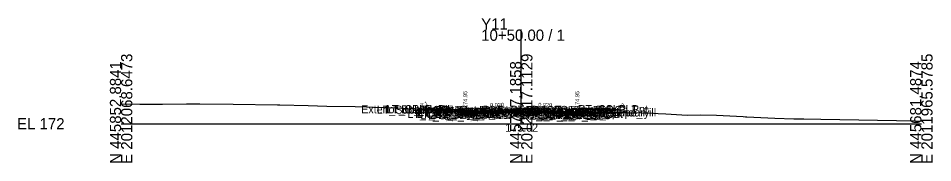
# Model space of a CAD drawing. Extents: x -26 to 203, y -10 to 3517.
# Drawn here: x -25.7 to 202.8, y 990.3 to 1026.3 of the extents above; entities that cross this region are included whole.
import ezdxf

# ---------------------------------------------------------------- set-up
doc = ezdxf.new("R2010")
doc.units = 0
for name, color, linetype in [('Default', 7, 'Continuous'), ('Exist CMT Pavement', 7, 'Continuous'), ('Exist Cross Section Cell', 7, 'Continuous'), ('Exist XS Center Line Elevation Label', 7, 'Continuous'), ('Exist XS Ground Line', 7, 'Continuous'), ('Prop CMT Conc Surface', 7, 'Continuous'), ('Prop CMT Concrete Structures', 7, 'Continuous'), ('Prop CMT Pvmt Course 1', 7, 'Continuous'), ('Prop CMT Pvmt Course 1 CG', 7, 'Continuous'), ('Prop CMT Pvmt Course 1 Wedge', 7, 'Continuous'), ('Prop CMT Pvmt Course 2', 7, 'Continuous'), ('Prop CMT Pvmt Course 2 Wedge', 7, 'Continuous'), ('Prop CMT Pvmt Course 3', 7, 'Continuous'), ('Prop CMT Pvmt Course 3 Wedge', 7, 'Continuous'), ('Prop CMT Pvmt Surface', 7, 'Continuous'), ('Prop CMT Pvmt Wedge Surface 1', 7, 'Continuous'), ('Prop CMT Pvmt Wedge Surface 2', 7, 'Continuous'), ('Prop CMT Pvmt Wedge Surface 3', 7, 'Continuous'), ('Prop CMT Slope Grass', 7, 'Continuous'), ('Prop CMT Subgrade Earthwork', 7, 'Continuous'), ('Prop XS Earthwork Shape', 7, 'Continuous'), ('Prop XS Hydro Elevations', 7, 'Continuous'), ('Prop XS SE Text', 7, 'Continuous'), ('Prop XS Side Slope Text', 7, 'Continuous'), ('Scratch_Level_0', 7, 'Continuous')]:
    doc.layers.add(name, color=color, linetype=linetype)

msp = doc.modelspace()

# ---------------------------------------------------------------- linework, layer by layer
at = {"layer": 'Exist CMT Pavement'}
msp.add_line((100, 1003.02), (110.98, 1002.65), dxfattribs=at)
msp.add_lwpolyline([(100, 1003.02), (99.41, 1003.04), (89.01, 1002.74)], dxfattribs=at)
at = {"layer": 'Exist Cross Section Cell'}
for p, q in [((100, 1000), (100, 1023.47)), ((0, 1000), (100, 1000)), ((100, 1000), (200, 1000))]:
    msp.add_line(p, q, dxfattribs=at)
at = {"layer": 'Exist XS Ground Line'}
msp.add_lwpolyline([(0, 1004.93), (4.7, 1004.9), (10.32, 1004.9), (16.37, 1005), (19.66, 1004.94), (28.04, 1004.91), (39.07, 1004.72), (39.71, 1004.7), (46.76, 1004.52), (51.38, 1004.41), (58.47, 1004.28), (61.33, 1004.19), (63.05, 1004.12), (68.62, 1003.94), (74.72, 1003.66), (77.51, 1003.51), (86.81, 1002.91), (87.99, 1002.76), (88.31, 1002.72), (94.9, 1002.9), (99.41, 1003.04), (100, 1003.02), (109.78, 1002.69), (111.37, 1002.63), (112.46, 1002.77), (114.66, 1002.75), (118.15, 1002.73), (126.92, 1002.83), (133.08, 1002.63), (134.21, 1002.59), (136.1, 1002.49), (141.5, 1002.16), (144.75, 1002.22), (148.79, 1002.18), (155.51, 1001.77), (156.07, 1001.73), (156.42, 1001.72), (163.36, 1001.43), (168.09, 1001.26), (170.65, 1001.22), (174.91, 1001.14), (198.53, 1000.71), (200, 1000.68)], dxfattribs=at)
at = {"layer": 'Prop CMT Conc Surface'}
for points in [[(86, 1002.95), (86, 1003.45), (85.5, 1003.45)], [(114, 1002.95), (114, 1003.45), (114.5, 1003.45)], [(88, 1003.07), (86, 1002.95)], [(112, 1003.07), (114, 1002.95)]]:
    msp.add_lwpolyline(points, dxfattribs=at)
at = {"layer": 'Prop CMT Concrete Structures'}
for points in [[(88, 1003.07), (86, 1002.95), (86, 1003.45), (85.5, 1003.45)], [(85.5, 1003.45), (85.5, 1002.44), (88, 1002.49)], [(112, 1003.07), (114, 1002.95), (114, 1003.45), (114.5, 1003.45)], [(114.5, 1003.45), (114.5, 1002.44), (112, 1002.49)], [(88, 1002.49), (88, 1003.07)], [(112, 1002.49), (112, 1003.07)]]:
    msp.add_lwpolyline(points, dxfattribs=at)
at = {"layer": 'Prop CMT Pvmt Course 1'}
for points in [[(100, 1003.31), (88, 1003.07)], [(100, 1003.06), (100, 1003.31)], [(100, 1003.31), (112, 1003.07)], [(100, 1003.06), (100, 1003.31)], [(88, 1003.07), (88, 1002.82)], [(88, 1002.82), (89, 1002.84)], [(89, 1002.97), (100, 1003.19)], [(89, 1002.84), (89, 1002.97)], [(100, 1003.19), (100, 1003.06), (100, 1003.06)], [(111, 1002.97), (100, 1003.19)], [(100, 1003.19), (100, 1003.06), (100, 1003.06)], [(111, 1002.84), (111, 1002.97)], [(112, 1002.82), (111, 1002.84)], [(112, 1003.07), (112, 1002.82)]]:
    msp.add_lwpolyline(points, dxfattribs=at)
at = {"layer": 'Prop CMT Pvmt Course 1 CG'}
for points in [[(88, 1002.49), (85, 1002.43), (84.7, 1002.13)], [(84.7, 1002.13), (88, 1002.2)], [(88, 1002.2), (88, 1002.49)], [(112, 1002.49), (115, 1002.43), (115.3, 1002.13)], [(112, 1002.2), (112, 1002.49)], [(115.3, 1002.13), (112, 1002.2)]]:
    msp.add_lwpolyline(points, dxfattribs=at)
at = {"layer": 'Prop CMT Pvmt Course 1 Wedge'}
for points in [[(100, 1003.19), (89, 1002.97)], [(100, 1003.19), (111, 1002.97)]]:
    msp.add_lwpolyline(points, dxfattribs=at)
at = {"layer": 'Prop CMT Pvmt Course 2'}
for points in [[(89, 1002.84), (88, 1002.82)], [(88, 1002.82), (88, 1002.57)], [(88, 1002.57), (89, 1002.59)], [(89, 1002.59), (89, 1002.84)], [(111, 1002.59), (111, 1002.84)], [(111, 1002.84), (112, 1002.82)], [(112, 1002.57), (111, 1002.59)], [(112, 1002.82), (112, 1002.57)]]:
    msp.add_lwpolyline(points, dxfattribs=at)
at = {"layer": 'Prop CMT Pvmt Course 2 Wedge'}
for points in [[(100, 1003.06), (89, 1002.84)], [(100, 1003.06), (111, 1002.84)]]:
    msp.add_lwpolyline(points, dxfattribs=at)
at = {"layer": 'Prop CMT Pvmt Course 3'}
for points in [[(89, 1002.59), (88, 1002.57)], [(88, 1002.57), (88, 1002.2)], [(88, 1002.2), (89, 1002.22)], [(89, 1002.22), (89, 1002.59)], [(111, 1002.59), (112, 1002.57)], [(111, 1002.22), (111, 1002.59)], [(112, 1002.2), (111, 1002.22)], [(112, 1002.57), (112, 1002.2)]]:
    msp.add_lwpolyline(points, dxfattribs=at)
at = {"layer": 'Prop CMT Pvmt Course 3 Wedge'}
for points in [[(100, 1002.81), (89, 1002.59)], [(100, 1002.81), (111, 1002.59)]]:
    msp.add_lwpolyline(points, dxfattribs=at)
at = {"layer": 'Prop CMT Pvmt Surface'}
for points in [[(100, 1003.31), (88, 1003.07)], [(100, 1003.31), (112, 1003.07)]]:
    msp.add_lwpolyline(points, dxfattribs=at)
at = {"layer": 'Prop CMT Pvmt Wedge Surface 1'}
for points in [[(88, 1002.82), (88, 1003.07)], [(89, 1002.84), (88, 1002.82)], [(100, 1003.19), (89, 1002.97)], [(89, 1002.97), (89, 1002.84)], [(100, 1003.19), (111, 1002.97)], [(111, 1002.97), (111, 1002.84)], [(111, 1002.84), (112, 1002.82)], [(112, 1002.82), (112, 1003.07)]]:
    msp.add_lwpolyline(points, dxfattribs=at)
at = {"layer": 'Prop CMT Pvmt Wedge Surface 2'}
for points in [[(88, 1002.82), (88, 1003.07)], [(100, 1003.06), (88, 1002.82)], [(100, 1003.06), (112, 1002.82)], [(112, 1002.82), (112, 1003.07)]]:
    msp.add_lwpolyline(points, dxfattribs=at)
at = {"layer": 'Prop CMT Pvmt Wedge Surface 3'}
for points in [[(88, 1002.57), (88, 1003.07)], [(100, 1002.81), (88, 1002.57)], [(100, 1002.81), (112, 1002.57)], [(112, 1002.57), (112, 1003.07)]]:
    msp.add_lwpolyline(points, dxfattribs=at)
at = {"layer": 'Prop CMT Slope Grass'}
for points in [[(85.5, 1003.45), (76, 1003.64), (75.87, 1003.6)], [(114.5, 1003.45), (124, 1003.64), (126.46, 1002.82)]]:
    msp.add_lwpolyline(points, dxfattribs=at)
at = {"layer": 'Prop CMT Subgrade Earthwork'}
for points in [[(88, 1002.2), (84.7, 1002.13), (83.34, 1003.5)], [(112, 1002.2), (115.3, 1002.13), (116.66, 1003.5)], [(89, 1002.22), (88, 1002.2)], [(89, 1002.22), (89.01, 1002.74)], [(111, 1002.22), (110.98, 1002.65)], [(111, 1002.22), (112, 1002.2)]]:
    msp.add_lwpolyline(points, dxfattribs=at)
at = {"layer": 'Prop XS Earthwork Shape'}
for points in [[(76, 1003.64), (75.87, 1003.6), (77.51, 1003.51), (83.73, 1003.1), (83.34, 1003.5)], [(115.91, 1002.75), (116.66, 1003.5), (124, 1003.64), (126.46, 1002.82), (118.15, 1002.73)], [(89, 1002.22), (88, 1002.2), (84.7, 1002.13), (83.73, 1003.1), (85.5, 1002.99), (85.5, 1002.44), (88, 1002.49), (87.99, 1002.76), (88.31, 1002.72), (89.01, 1002.74)], [(86.08, 1002.96), (86, 1002.95), (85.5, 1002.99), (85.5, 1002.44), (88, 1002.49), (87.99, 1002.76), (86.81, 1002.91)], [(94.9, 1002.9), (99.41, 1003.04), (89.01, 1002.74)], [(100, 1003.02), (110.98, 1002.65), (109.78, 1002.69)], [(114.5, 1002.75), (114.5, 1002.44), (112, 1002.49), (112, 1002.71), (111.37, 1002.63), (110.98, 1002.65), (111, 1002.22), (112, 1002.2), (115.3, 1002.13), (115.91, 1002.75), (114.66, 1002.75)], [(114.5, 1002.75), (114.5, 1002.44), (112, 1002.49), (112, 1002.71), (112.46, 1002.77)]]:
    msp.add_lwpolyline(points, close=True, dxfattribs=at)

# ---------------------------------------------------------------- texts
at = {"layer": 'Default'}
msp.add_text('-', height=0.0001, dxfattribs=at).set_placement((0, 1000))
at = {"layer": 'Exist Cross Section Cell'}
for s, p in [('Y11', (90, 1023.47)), ('10+50.00 / 1', (90, 1020.67)), ('EL 172', (-26, 998.6))]:
    msp.add_text(s, height=2.8, dxfattribs=at).set_placement(p)
for s, p in [('E 2012068.6473', (2.8, 990)), ('E 2012017.1129', (102.8, 990)), ('E 2011965.5785', (202.8, 990)), ('N 445852.8841', (0, 990)), ('N 445767.1858', (100, 990)), ('N 445681.4874', (200, 990))]:
    msp.add_text(s, height=2.8, rotation=90, dxfattribs=at).set_placement(p)
at = {"layer": 'Exist XS Center Line Elevation Label'}
msp.add_text('175.02', height=2, dxfattribs=at).set_placement((96.03, 998.02))
at = {"layer": 'Prop XS Hydro Elevations'}
for p in [(86.5, 1003.95), (114.5, 1003.95)]:
    msp.add_text('174.95', height=1, rotation=90, dxfattribs=at).set_placement(p)
at = {"layer": 'Prop XS SE Text'}
for rotation, p in [(1.1458, (92.23, 1004.16)), (358.8542, (104.27, 1004.23))]:
    msp.add_text('0.020', height=1, rotation=rotation, dxfattribs=at).set_placement(p)
at = {"layer": 'Prop XS Side Slope Text'}
for rotation, p in [(18.4332, (74.94, 1004.08)), (341.5668, (124.72, 1004.2))]:
    msp.add_text('3:1', height=1, rotation=rotation, dxfattribs=at).set_placement(p)
at = {"layer": 'Scratch_Level_0'}
for s, p in [('Exterior Boundary', (60.01, 1002.6)), ('LT_Sub_Trench_Out_DLT', (63.91, 1002.5)), ('LT_CSLP_Pnt', (66.17, 1002.64)), ('LT_Slope_Fill', (66.39, 1002.6)), ('LT_CG1_Shelf_Out', (71.55, 1001.43)), ('LT_CG_Top_Face', (73.26, 1002.45)), ('LT_CG_Top_BOC', (73.78, 1002.45)), ('LT_CG_Bot_BOC', (73.81, 1001.44)), ('LT_PV_Sub_Tie_Out', (73.96, 1001.74)), ('LT_CG_Top_Gut', (74.24, 1001.95)), ('LT_PV_OEEOP_EG', (76.54, 1001.74)), ('LT_CG_Bot_IE', (77.91, 1001.49)), ('LT_Sub_OEOT', (78.08, 1001.2)), ('LT_PV2_OEOT', (78.17, 1001.82)), ('LT_PV3_OEOT', (78.17, 1001.57)), ('LT_Sub_OEEOP', (78.21, 1001.22)), ('LT_PV2_OEEOP', (78.31, 1001.84)), ('LT_PV3_OEEOP', (78.31, 1001.59)), ('LT_PV1_OEOT', (78.74, 1002.07)), ('LT_PV1_OEEOP', (78.87, 1001.97)), ('RT_PV_IEEOP_EG', (88.14, 1002.02)), ('LT_PV_IEEOP_EG', (88.19, 1002.02)), ('RT_PV2_IEEOP', (89.91, 1002.06)), ('RT_PV3_IEEOP', (89.91, 1001.81)), ('LT_PV2_IEEOP', (89.95, 1002.06)), ('LT_PV3_IEEOP', (89.95, 1001.81)), ('RT_PV1_IEEOP', (90.47, 1002.19)), ('LT_PV1_IEEOP', (90.52, 1002.19)), ('PV2_PGL', (93.91, 1002.06)), ('PV1_PGL', (94.47, 1002.31)), ('RT_PV_Sub_Tie_Out', (95.88, 1001.65)), ('RT_Sub_Trench_Out_DLT', (97.18, 1002.5)), ('RT_PV_OEEOP_EG', (98.5, 1001.64)), ('RT_Sub_OEEOP', (100.17, 1001.22)), ('RT_PV2_OEEOP', (100.26, 1001.84)), ('RT_PV3_OEEOP', (100.26, 1001.59)), ('RT_PV1_OEEOP', (100.83, 1001.97)), ('RT_CG_Top_Face', (101.21, 1002.45)), ('RT_CG1_Shelf_Out', (101.5, 1001.43)), ('RT_CG_Bot_IE', (101.87, 1001.49)), ('RT_Sub_OEOT', (102.03, 1001.2)), ('RT_PV2_OEOT', (102.13, 1001.82)), ('RT_PV3_OEOT', (102.13, 1001.57)), ('RT_CG_Top_Gut', (102.19, 1001.95)), ('RT_PV1_OEOT', (102.69, 1002.07)), ('RT_CG_Top_BOC', (102.74, 1002.45)), ('RT_CG_Bot_BOC', (102.77, 1001.44)), ('Exterior Boundary', (110.6, 1001.82)), ('RT_CSLP_Pnt', (114.13, 1002.64)), ('RT_Slope_Fill', (116.93, 1001.82)), ('LT_Sub_OEOP', (74.81, 1001.13)), ('RT_Sub_OEOP', (105.36, 1001.13))]:
    msp.add_text(s, height=2, dxfattribs=at).set_placement(p)

doc.saveas('drawing.dxf')
